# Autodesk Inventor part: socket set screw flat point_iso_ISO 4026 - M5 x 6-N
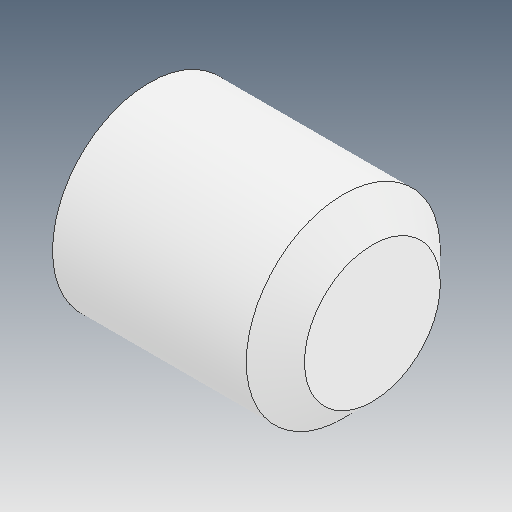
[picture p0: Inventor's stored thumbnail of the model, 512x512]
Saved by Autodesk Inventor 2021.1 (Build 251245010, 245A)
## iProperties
Created: 2021-05
Part Number: socket set screw flat point_iso_ISO 4026 - M5 x 6-N
Material: Ogólny
Document SubType Name: Modeling
Designer: user
Density: 1 g/cm^3
Appearance: Domyślna
Author: user
Revision Number: ÈÎºÎ
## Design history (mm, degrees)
feature "ÊäÈë1"
node "Bryła1"
